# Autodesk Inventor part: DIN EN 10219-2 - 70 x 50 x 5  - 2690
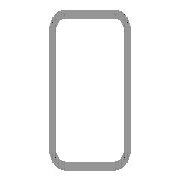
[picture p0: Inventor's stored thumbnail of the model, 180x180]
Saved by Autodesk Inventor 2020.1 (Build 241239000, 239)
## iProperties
_CCFamilyMember: 17
_CCFamilyDisplayName: DIN EN 10219-2 (Rechteckiges Hohlprofil - Kaltgeformt) - Kaltgeformte, geschweißte Baustahl-Hohlprofile aus unlegiertem Feinkorn-Baustahl
_FrameMemberDoc: Frame Member File
_Version: 15.0.0
_GetPNFromCC: 1
Created: 2019-01
Part Number: DIN EN 10219-2 - 70 x 50 x 5  - 2690
Material: Stahl, weich
Description: Kaltgeformte, geschweißte Baustahl-Hohlprofile aus unlegiertem Feinkorn-Baustahl
Document SubType Name: Modeling
Standard: DIN
Designer: lutzd
Standard Revision: 2006-07
Standards Organization: DIN
Language: de-DE
Size Designation: 70 x 50 x 5
Categories: <MemberInstance><Categories><Category DisplayName="Profile" InternalName="089c4875-fa83-4c05-b084-43b9cc11f5ed" Mnemonic="GRDR"><CategoryParameter DisplayName="
Stock Number: 70 x 50 x 5
Mass: 21852.3 g
Surface Area: 11168.2 cm^2
Volume: 2783.73 cm^3
Density: 7.85 g/cm^3
Appearance: Halbpoliert
IsCustomPart: 1
G_L: 2690,000 mm
G_W: 50,000 mm
G_H: 70,000 mm
DocNumber: ADSK-014146
Folder: .
Dimensions: 50x70x2690 mm
Mass: 21,852 kg
Title: Profil-Bauteil
Author: lutzd
Revision Number: -
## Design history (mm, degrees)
node "Startebene"
node "Endebene"
sketch "Skizze"
  geometry: L1 (-25, -25)-(-25, 25); L2 (-15, 35)-(15, 35); L3 (25, 25)-(25, -25); L4 (15, -35)-(-15, -35); L5 (-15, 30)-(15, 30); L6 (20, 25)-(20, -25); L7 (15, -30)-(-15, -30); L8 (-20, -25)-(-20, 25); L9 (0, 51.899)-(0, -51.899) reference; L10 (-37.899, 0)-(37.899, 0) reference; A1 r 10 centre (-15, -25) between (-25, -25) and (-15, -35); A2 r 10 centre (-15, 25) between (-15, 35) and (-25, 25); A3 r 10 centre (15, 25) between (25, 25) and (15, 35); A4 r 10 centre (15, -25) between (15, -35) and (25, -25); A5 r 5 centre (-15, 25) between (-15, 30) and (-20, 25); A6 r 5 centre (15, 25) between (20, 25) and (15, 30); A7 r 5 centre (15, -25) between (15, -30) and (20, -25); A8 r 5 centre (-15, -25) between (-20, -25) and (-15, -30)
  constraints: 16 end point, 16 point on circle, 8 centre point, 8 tangent, 4 parallel, 3 equal radius, 2 perpendicular, 7 other
  dimensions: "d7" = 10 radius of A1 (= G_IR); "d10" = 70 distance between parallel lines of L2 L4 (= G_H); "d11" = 50 distance between parallel lines of L1 L3 (= G_W); "d12" = 5 distance between parallel lines of L3 L6 (= G_T); "d15" = 35 distance between parallel lines of L2 L10 (= 0.5 x d10); "d16" = 25 distance between parallel lines of L9 L3 (= 0.5 x d11)
extrude "Körper" new body sketch "Skizze" stored distance "d3" = 2690 (= G_L); taper "d4" = 0 deg
node "Driven Length"
  sketch "Sketch3"
    geometry: L1 (0, 0)-(10, 0) reference
    constraints: 2 end point, 1 horizontal
  workplane "Work Plane3"
  sketch "Sketch4"
    geometry: L1 (-2, 0)-(12, 0) reference; L2 (-2, 2690)-(12, 2690) reference
    dimensions: "d18" = 2690 distance between parallel lines of L1 L2 (derived)
sketch "Skizze5"
  geometry: L1 (0, -50)-(0, 0) reference; 13 further points
  constraints: 10 horizontal alignment, 6 vertical alignment
  dimensions: "d19" = 38 distance of point (187.5, -44) point (187.5, -6); "d20" = 19 vertical distance of point (0, -25) point (187.5, -6) (= 0.5 x d19); "d21" = 187.5 distance from line of L1 point (187.5, -6); "d22" = 399.5 distance of point (587, -6) point (187.5, -6); "d23" = 523 distance of point (587, -6) point (1110, -6); "d24" = 463 distance of point (1573, -6) point (1110, -6); "d25" = 399.5 distance of point (1573, -44) point (1972.5, -44) (= d22); "d26" = 163.5 horizontal distance of point (2136, -6) point (1972.5, -44)
hole "Bohrung1" sketch "Skizze5" at (187.5, -6), (587, -6), (1110, -6), (1573, -6), (2136, -6), (1972.5, -6), (187.5, -44), (587, -44), (1110, -44), (1573, -44), (2136, -44), (1972.5, -44) diameter "d27" = 6.647; stored, may be unused: countersink angle "d31" = 90 deg, drill point angle "d33" = 0 deg; dims "d28" = 16, "d29" = 4, "d30" = 2, "d32" = 22.2
body "Solid1"
other parameters: "G_W" = 50 [user parameter; used in 1 equation term], "G_H" = 70 [user parameter; used in 1 equation term], "G_T" = 5 [user parameter; used in 1 equation term], "G_IR" = 10 [user parameter; used in 1 equation term], "G_L" = 2690 (= d18) [user parameter; used in 1 equation term], "G_OFFSET_START" = 0 [user parameter; used in 1 equation term], "G_OFFSET_END" = 0 [user parameter; used in 1 equation term], "d13" = 0 (computed from G_OFFSET_START), "d17" = 90 deg
